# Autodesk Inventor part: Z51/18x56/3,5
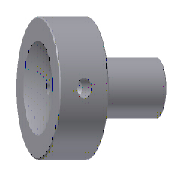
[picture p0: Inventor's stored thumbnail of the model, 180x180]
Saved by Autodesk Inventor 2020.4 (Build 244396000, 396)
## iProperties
Created: 2019-01
Part Number: Z51/18x56/3,5
Material: 1.2826
Description: Sprue Bushing
Document SubType Name: Modeling
Designer: mel
Standard Revision: 1
Manufacturer: HASCO
Language: fr-FR
Size Designation: 18x56/3,5
Categories: <MemberInstance><Categories><Category DisplayName="Moule" InternalName="349578f2-f4d4-4954-8c09-8e99297a61c0" Mnemonic="MOLD"><Category DisplayName="Canal d'inj
Density: 7.82 g/cm^3
Appearance: Par défaut
Mass: 449.949 g
Surface Area: 98.7904 cm^2
Volume: 57.5383 cm^3
IsCustomPart: 1
Author: mel
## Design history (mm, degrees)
sketch "Sketch1"
  geometry: L1 (0, -27.2)-(0, 23.2) reference; L2 (1.75, 18)-(19, 18); L3 (19, 18)-(19, 0); L4 (19, 0)-(12, 0); L5 (9, -3)-(9, -56); L6 (9, -56)-(3.688, -56); L7 (3.688, -56)-(1.75, 18); A1 r 3 centre (12, -3) between (12, 0) and (9, -3); 2 further points
  constraints: 12 end point, 3 parallel, 2 perpendicular, 2 point on circle, 2 point on line, 2 tangent, 1 centre point
  dimensions: "d0" = 18 diameter of L5 L1 (= D); "d3" = 38 diameter of L3 L1 (= d1); "d6" = 1.5 deg angle of L7 L1 (= 0.5 x Taper); "d7" = 18 distance between parallel lines of L4 L2 (= K_); "d8" = 56 distance between parallel lines of L4 L6 (= L); "d9" = 3 radius of A1 (= R3); "d62" = 3.5 diameter of point (1.75, 18) L1 (= d_); "d63" = 0 distance from line of point (1.75, 18) L2 (computed from Rd)
revolve "Revolution1" sketch "Sketch1" stored, may be unused: angle "d10" = 90 deg
sketch "Sketch2"
  geometry: L1 (0, -32.79)-(0, 56.739) reference; L2 (3.688, -56)-(1.75, 18) reference; L3 (-19, 18)-(19, 18) reference; L4 (0, 48.901)-(0, 17.901); A1 r 15.5 centre (0, 33.401) between (0, 17.901) and (0, 48.901); 2 further points
  constraints: 3 point on circle, 3 point on line, 2 end point, 1 centre point, 1 midpoint
  dimensions: "d64" = 0 distance from line of point (1.75, 18) L3 (computed from Rd); "d67" = 15.5 radius of A1 (= Rk)
revolve "Revolution2" sketch "Sketch2" stored, may be unused: angle "d13" = 90 deg
workplane "Work Plane1"
sketch "Sketch3"
  geometry: 2 further points
  constraints: 1 vertical alignment
  dimensions: "d43" = 9 distance of point (0, -9) point (0, 0) (= 0.5 x K_)
hole "Hole1" sketch "Sketch3" at (0, 0) diameter "d15" = 4 (= pd1); stored, may be unused: countersink angle "d19" = 90 deg, drill point angle "d21" = 118 deg; dims "d16" = 6, "d17" = 4, "d18" = 2, "d20" = 6 (= pl1)
chamfer "Chamfer1" distance "d22" = 0.3; stored, may be unused: second distance "d23" = 2, angle "d24" = 45 deg
sketch "Sketch4"
  geometry: L1 (0, -30.4)-(0, 42.4) reference; L2 (0, 36)-(19.5, 36); L3 (19.5, 36)-(19.5, 0); L4 (9, -56)-(0, -56); L5 (0, -56)-(0, 36); L6 (9, -3)-(9, -56); L7 (12, 0)-(19.5, 0); L8 (12, 0)-(9, -3); 2 further points
  constraints: 14 end point, 4 point on line, 2 horizontal, 2 parallel, 1 perpendicular, 1 vertical
  dimensions: "d56" = 3 distance of L7.start point (9, 0) (= R3_CS); "d57" = 3 distance of L6.start point (9, 0) (= d56); "d58" = 39 diameter of L3 L1 (= d1_CS); "d59" = 36 distance between parallel lines of L7 L2 (= K_CS); "d60" = 18 diameter of L6 L1 (= D_CS); "d61" = 56 distance between parallel lines of L7 L4 (= L_CS)
feature "RevolutionSrf1" sketch "Sketch4" dims angle "d33" = 90 deg
feature "Sculpter1"
body "Solid1"
body "Srf1"
feature "Surface1"
body "Srf2"
other parameters: "L" = 56 [user parameter; used in 1 equation term], "d1" = 38 [user parameter; used in 1 equation term], "d_" = 3.5 [user parameter; used in 1 equation term], "D" = 18 [user parameter; used in 1 equation term], "K_" = 18 [user parameter; used in 2 equation terms], "R" = 0 [user parameter], "Taper" = 3 deg [user parameter; used in 1 equation term], "Rd" = 0 [user parameter; used in 2 equation terms], "R3" = 3 [user parameter; used in 1 equation term], "pd1" = 4 [user parameter; used in 1 equation term], "d1_CS" = 39 [user parameter; used in 1 equation term], "K_CS" = 36 [user parameter; used in 1 equation term], "d44" = 0, "d45" = 0, "d46" = 0, "L_CS" = 56 [user parameter; used in 1 equation term], "D_CS" = 18 [user parameter; used in 1 equation term], "pl1" = 6 [user parameter; used in 1 equation term], "R3_CS" = 3 [user parameter; used in 1 equation term], "Rk" = 15.5 [user parameter; used in 1 equation term]
